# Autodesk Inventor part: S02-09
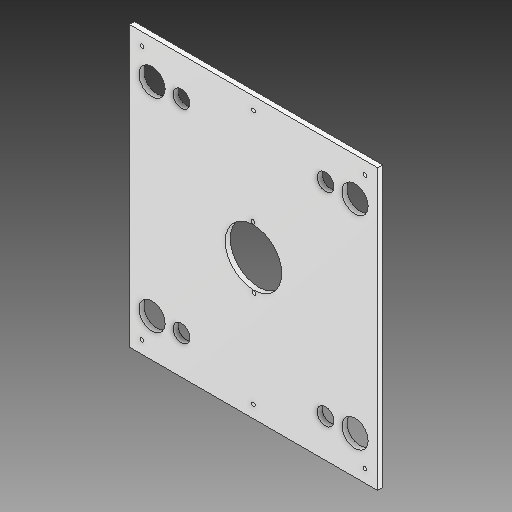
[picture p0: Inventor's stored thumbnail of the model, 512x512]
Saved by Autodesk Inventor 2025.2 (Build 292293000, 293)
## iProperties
Created: 2025-04
Part Number: S02-09
Material: Všeobecné
Document SubType Name: Modeling
Designer: Patrik
Density: 1 g/cm^3
Appearance: Výchozí
Description: Deska izolační levá
Stock Number: E 1402/446 396/324/230/324
Mass: 1296.51 g
Surface Area: 3481.62 cm^2
Volume: 1296.51 cm^3
Author: Patrik
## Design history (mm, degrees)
feature "Base1"
feature "Vyřezání1"
node "Těleso1"
feature "Plocha1"
node "Povrch1"
